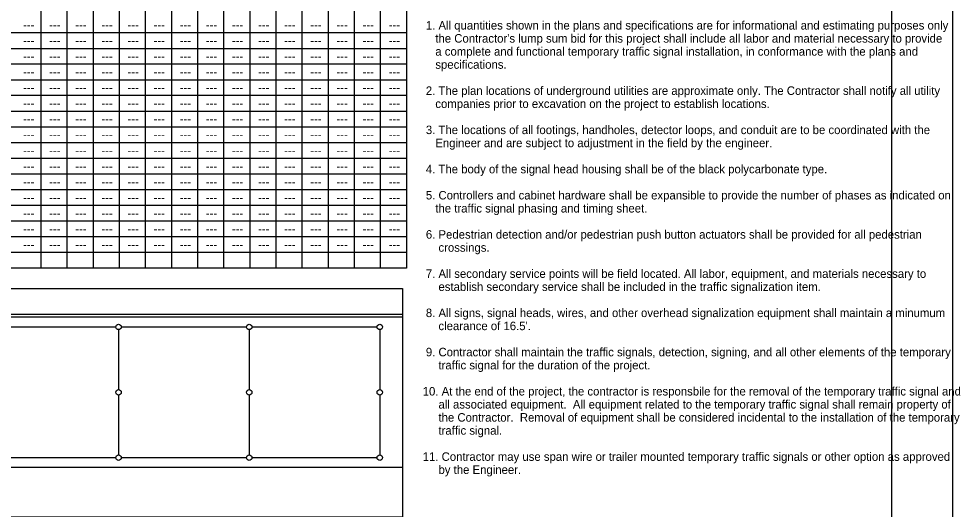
# Model space of a CAD drawing. Extents: x 10040 to 81668, y 7194 to 11018.
# Drawn here: x 11931 to 13373, y 8516 to 9266 of the extents above; entities that cross this region are included whole.
import ezdxf

# ---------------------------------------------------------------- set-up
doc = ezdxf.new("R2010")
doc.units = 0
for name, color, linetype in [('dsnCellElements', 7, 'Continuous'), ('dsnStdTable', 7, 'Continuous'), ('Level 3', 7, 'Continuous'), ('Level 4', 7, 'Continuous'), ('wetSpecialNote', 7, 'Continuous')]:
    doc.layers.add(name, color=color, linetype=linetype)

msp = doc.modelspace()

# ---------------------------------------------------------------- linework, layer by layer
at = {"layer": 'dsnCellElements'}
msp.add_lwpolyline([(10039.6, 10000), (13360.5, 10000), (13360.5, 7806.6), (10039.6, 7806.6)], close=True, dxfattribs=at)
at = {"layer": 'Level 3'}
msp.add_lwpolyline([(10132.5, 9944), (13267.5, 9944), (13267.5, 7924), (10132.5, 7924)], close=True, dxfattribs=at)
msp.add_lwpolyline([(10132.5, 9944), (13267.5, 9944), (13267.5, 7924), (10132.5, 7924)], close=True, dxfattribs=at)
at = {"layer": 'Level 4'}
for p, q in [((12124.5, 9889), (12124.5, 8885)), ((12124.5, 9889), (12124.5, 8885)), ((12324.5, 9889), (12324.5, 8885)), ((12324.5, 9889), (12324.5, 8885)), ((11964.5, 9665), (11964.5, 8885)), ((12164.5, 9665), (12164.5, 8885)), ((12364.5, 9665), (12364.5, 8885)), ((12004.5, 9641), (12004.5, 8885)), ((12044.5, 9641), (12044.5, 8885)), ((12084.5, 9641), (12084.5, 8885)), ((12204.5, 9641), (12204.5, 8885)), ((12244.5, 9641), (12244.5, 8885)), ((12284.5, 9641), (12284.5, 8885)), ((12404.5, 9641), (12404.5, 8885)), ((12444.5, 9641), (12444.5, 8885)), ((12484.5, 9641), (12484.5, 8885)), ((12518.3, 8809.8), (10868.3, 8809.8)), ((11887.7, 8794.8), (12079.5, 8794.8)), ((12087.7, 8794.8), (12279.5, 8794.8)), ((12287.8, 8794.8), (12479.6, 8794.8)), ((12083.6, 8790.7), (12083.6, 8698.9)), ((12283.7, 8790.7), (12283.7, 8698.9)), ((12483.7, 8790.7), (12483.7, 8698.9)), ((12083.6, 8690.7), (12083.6, 8598.9)), ((12283.7, 8690.7), (12283.7, 8598.9)), ((12483.7, 8690.7), (12483.7, 8598.9)), ((11887.7, 8594.8), (12079.5, 8594.8)), ((12087.7, 8594.8), (12279.5, 8594.8)), ((12287.8, 8594.8), (12479.6, 8594.8)), ((12518.3, 8579.8), (10868.3, 8579.8))]:
    msp.add_line(p, q, dxfattribs=at)
for points in [[(10664.5, 9929), (12524.5, 9929), (12524.5, 8885), (10664.5, 8885)], [(10868.3, 8853.8), (12518.3, 8853.8), (12518.3, 8503.8), (10868.3, 8503.8)]]:
    msp.add_lwpolyline(points, close=True, dxfattribs=at)
msp.add_lwpolyline([(12518.3, 8813.8), (10868.3, 8813.8)], dxfattribs=at)
for centre in [(12083.6, 8794.8), (12283.7, 8794.8), (12483.7, 8794.8), (12083.6, 8694.8), (12283.7, 8694.8), (12483.7, 8694.8), (12083.6, 8594.8), (12283.7, 8594.8), (12483.7, 8594.8)]:
    msp.add_circle(centre, 4.13, dxfattribs=at)
at = {"layer": 'wetSpecialNote'}
for p, q in [((12524.5, 9245), (10664.5, 9245)), ((10824.5, 9221), (12524.5, 9221)), ((12524.5, 9197), (10824.5, 9197)), ((10824.5, 9173), (12524.5, 9173)), ((12524.5, 9149), (10824.5, 9149)), ((10664.5, 9125), (12524.5, 9125)), ((10824.5, 9101), (12524.5, 9101)), ((10824.5, 9077), (12524.5, 9077)), ((10824.5, 9053), (12524.5, 9053)), ((10824.5, 9029), (12524.5, 9029)), ((10664.5, 9005), (12524.5, 9005)), ((10824.5, 8981), (12524.5, 8981)), ((10824.5, 8957), (12524.5, 8957)), ((10824.5, 8933), (12524.5, 8933)), ((10824.5, 8909), (12524.5, 8909))]:
    msp.add_line(p, q, dxfattribs=at)

# ---------------------------------------------------------------- texts
at = {"layer": 'dsnStdTable'}
for p in [(11937.3, 9250.5), (11977.3, 9250.5), (12017.3, 9250.5), (12057.3, 9250.5), (12097.3, 9250.5), (12137.3, 9250.5), (12177.3, 9250.5), (12217.3, 9250.5), (12257.3, 9250.5), (12297.3, 9250.5), (12337.3, 9250.5), (12377.3, 9250.5), (12417.3, 9250.5), (12457.3, 9250.5), (12497.3, 9250.5), (11937.3, 9226.5), (11977.3, 9226.5), (12017.3, 9226.5), (12057.3, 9226.5), (12097.3, 9226.5), (12137.3, 9226.5), (12177.3, 9226.5), (12217.3, 9226.5), (12257.3, 9226.5), (12297.3, 9226.5), (12337.3, 9226.5), (12377.3, 9226.5), (12417.3, 9226.5), (12457.3, 9226.5), (12497.3, 9226.5), (11937.3, 9202.5), (11977.3, 9202.5), (12017.3, 9202.5), (12057.3, 9202.5), (12097.3, 9202.5), (12137.3, 9202.5), (12177.3, 9202.5), (12217.3, 9202.5), (12257.3, 9202.5), (12297.3, 9202.5), (12337.3, 9202.5), (12377.3, 9202.5), (12417.3, 9202.5), (12457.3, 9202.5), (12497.3, 9202.5), (11937.3, 9178.5), (11977.3, 9178.5), (12017.3, 9178.5), (12057.3, 9178.5), (12097.3, 9178.5), (12137.3, 9178.5), (12177.3, 9178.5), (12217.3, 9178.5), (12257.3, 9178.5), (12297.3, 9178.5), (12337.3, 9178.5), (12377.3, 9178.5), (12417.3, 9178.5), (12457.3, 9178.5), (12497.3, 9178.5), (11937.3, 9154.5), (11977.3, 9154.5), (12017.3, 9154.5), (12057.3, 9154.5), (12097.3, 9154.5), (12137.3, 9154.5), (12177.3, 9154.5), (12217.3, 9154.5), (12257.3, 9154.5), (12297.3, 9154.5), (12337.3, 9154.5), (12377.3, 9154.5), (12417.3, 9154.5), (12457.3, 9154.5), (12497.3, 9154.5), (11937.3, 9130.5), (11977.3, 9130.5), (12017.3, 9130.5), (12057.3, 9130.5), (12097.3, 9130.5), (12137.3, 9130.5), (12177.3, 9130.5), (12217.3, 9130.5), (12257.3, 9130.5), (12297.3, 9130.5), (12337.3, 9130.5), (12377.3, 9130.5), (12417.3, 9130.5), (12457.3, 9130.5), (12497.3, 9130.5), (11937.3, 9106.5), (11977.3, 9106.5), (12017.3, 9106.5), (12057.3, 9106.5), (12097.3, 9106.5), (12137.3, 9106.5), (12177.3, 9106.5), (12217.3, 9106.5), (12257.3, 9106.5), (12297.3, 9106.5), (12337.3, 9106.5), (12377.3, 9106.5), (12417.3, 9106.5), (12457.3, 9106.5), (12497.3, 9106.5), (11937.3, 9082.5), (11977.3, 9082.5), (12017.3, 9082.5), (12057.3, 9082.5), (12097.3, 9082.5), (12137.3, 9082.5), (12177.3, 9082.5), (12217.3, 9082.5), (12257.3, 9082.5), (12297.3, 9082.5), (12337.3, 9082.5), (12377.3, 9082.5), (12417.3, 9082.5), (12457.3, 9082.5), (12497.3, 9082.5), (11937.3, 9058.5), (11977.3, 9058.5), (12017.3, 9058.5), (12057.3, 9058.5), (12097.3, 9058.5), (12137.3, 9058.5), (12177.3, 9058.5), (12217.3, 9058.5), (12257.3, 9058.5), (12297.3, 9058.5), (12337.3, 9058.5), (12377.3, 9058.5), (12417.3, 9058.5), (12457.3, 9058.5), (12497.3, 9058.5), (11937.3, 9034.5), (11977.3, 9034.5), (12017.3, 9034.5), (12057.3, 9034.5), (12097.3, 9034.5), (12137.3, 9034.5), (12177.3, 9034.5), (12217.3, 9034.5), (12257.3, 9034.5), (12297.3, 9034.5), (12337.3, 9034.5), (12377.3, 9034.5), (12417.3, 9034.5), (12457.3, 9034.5), (12497.3, 9034.5), (11937.3, 9010.5), (11977.3, 9010.5), (12017.3, 9010.5), (12057.3, 9010.5), (12097.3, 9010.5), (12137.3, 9010.5), (12177.3, 9010.5), (12217.3, 9010.5), (12257.3, 9010.5), (12297.3, 9010.5), (12337.3, 9010.5), (12377.3, 9010.5), (12417.3, 9010.5), (12457.3, 9010.5), (12497.3, 9010.5), (11937.3, 8986.5), (11977.3, 8986.5), (12017.3, 8986.5), (12057.3, 8986.5), (12097.3, 8986.5), (12137.3, 8986.5), (12177.3, 8986.5), (12217.3, 8986.5), (12257.3, 8986.5), (12297.3, 8986.5), (12337.3, 8986.5), (12377.3, 8986.5), (12417.3, 8986.5), (12457.3, 8986.5), (12497.3, 8986.5), (11937.3, 8962.5), (11977.3, 8962.5), (12017.3, 8962.5), (12057.3, 8962.5), (12097.3, 8962.5), (12137.3, 8962.5), (12177.3, 8962.5), (12217.3, 8962.5), (12257.3, 8962.5), (12297.3, 8962.5), (12337.3, 8962.5), (12377.3, 8962.5), (12417.3, 8962.5), (12457.3, 8962.5), (12497.3, 8962.5), (11937.3, 8938.5), (11977.3, 8938.5), (12017.3, 8938.5), (12057.3, 8938.5), (12097.3, 8938.5), (12137.3, 8938.5), (12177.3, 8938.5), (12217.3, 8938.5), (12257.3, 8938.5), (12297.3, 8938.5), (12337.3, 8938.5), (12377.3, 8938.5), (12417.3, 8938.5), (12457.3, 8938.5), (12497.3, 8938.5), (11937.3, 8914.5), (11977.3, 8914.5), (12017.3, 8914.5), (12057.3, 8914.5), (12097.3, 8914.5), (12137.3, 8914.5), (12177.3, 8914.5), (12217.3, 8914.5), (12257.3, 8914.5), (12297.3, 8914.5), (12337.3, 8914.5), (12377.3, 8914.5), (12417.3, 8914.5), (12457.3, 8914.5), (12497.3, 8914.5)]:
    msp.add_text('---', height=13, dxfattribs=at).set_placement(p)
at = {"layer": 'wetSpecialNote'}
for s, p in [(' 1. All quantities shown in the plans and specifications are for informational and estimating purposes only', (12549.4, 9249.9)), ("    the Contractor's lump sum bid for this project shall include all labor and material necessary to provide", (12549.4, 9229.9)), ('    a complete and functional temporary traffic signal installation, in conformance with the plans and', (12549.4, 9209.9)), ('    specifications.', (12549.4, 9189.9)), (' 2. The plan locations of underground utilities are approximate only. The Contractor shall notify all utility', (12549.4, 9149.9)), ('    companies prior to excavation on the project to establish locations.', (12549.4, 9129.9)), (' 3. The locations of all footings, handholes, detector loops, and conduit are to be coordinated with the', (12549.4, 9089.9)), ('    Engineer and are subject to adjustment in the field by the engineer.  ', (12549.4, 9069.9)), (' 4. The body of the signal head housing shall be of the black polycarbonate type.', (12549.4, 9029.9)), (' 5. Controllers and cabinet hardware shall be expansible to provide the number of phases as indicated on', (12549.4, 8989.9)), ('    the traffic signal phasing and timing sheet.', (12549.4, 8969.9)), (' 6. Pedestrian detection and/or pedestrian push button actuators shall be provided for all pedestrian', (12549.4, 8929.9)), ('     crossings.', (12549.4, 8909.9)), (' 7. All secondary service points will be field located. All labor, equipment, and materials necessary to ', (12549.4, 8869.9)), ('     establish secondary service shall be included in the traffic signalization item.', (12549.4, 8849.9)), (' 8. All signs, signal heads, wires, and other overhead signalization equipment shall maintain a minumum', (12549.4, 8809.9)), ("     clearance of 16.5'.", (12549.4, 8789.9)), (' 9. Contractor shall maintain the traffic signals, detection, signing, and all other elements of the temporary', (12549.4, 8749.9)), ('     traffic signal for the duration of the project.', (12549.4, 8729.9)), ('10. At the end of the project, the contractor is responsbile for the removal of the temporary traffic signal and', (12549.4, 8689.9)), ('     all associated equipment.  All equipment related to the temporary traffic signal shall remain property of ', (12549.4, 8669.9)), ('     the Contractor.  Removal of equipment shall be considered incidental to the installation of the temporary', (12549.4, 8649.9)), ('     traffic signal.', (12549.4, 8629.9)), ('11. Contractor may use span wire or trailer mounted temporary traffic signals or other option as approved', (12549.4, 8589.9)), ('     by the Engineer.', (12549.4, 8569.9))]:
    msp.add_text(s, height=13, rotation=360, dxfattribs=at).set_placement(p)

doc.saveas('drawing.dxf')
